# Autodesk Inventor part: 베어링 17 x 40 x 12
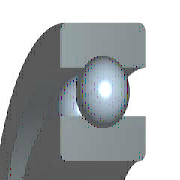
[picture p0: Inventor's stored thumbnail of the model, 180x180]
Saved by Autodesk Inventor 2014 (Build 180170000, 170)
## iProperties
IsCustomPart: 1
Created: 2012-02
Part Number: 베어링 17 x 40 x 12
Material: 강철, 연강
Description: 깊은 그루브 볼 베어링
Document SubType Name: Modeling
Standard: KS B 2023
Designer: mduedu
Standards Organization: KS
Language: ko-KR
Size Designation: 6203 - 17 x 40 x 12
Categories: <MemberInstance><Categories><Category DisplayName="샤프트 부품" InternalName="7f7aeb1f-a693-4053-b835-cee3144e0d98" Mnemonic="SHFT"><Category DisplayName="베어링" Inter
Density: 1 g/cm^3
Appearance: 노란색
Author: mduedu
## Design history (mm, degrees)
sketch "스케치" dims "d0" = 5.98 (= -0.26 x WD + 0.26 x BD)
  geometry: L1 (3.01, 14.25)-(8.99, 14.25); L2 (6, 14.25)-(6, 11.26); L3 (6, 14.25)-(6, 17.24); L4 (3.778, 12.249)-(0, 12.249); L5 (0, 8.5)-(12, 8.5); L6 (3.778, 16.251)-(0, 16.251); L7 (0, 20)-(12, 20); L8 (12, 8.5)-(12, 12.249); L9 (8.222, 12.249)-(12, 12.249); L10 (8.222, 16.251)-(12, 16.251); L11 (12, 20)-(12, 16.251); L12 (-1.4, 0)-(8.4, 0) reference; L13 (0, -0.3)-(0, 5.3) reference
  constraints: 22 end point, 4 point on line, 2 collinear, 2 perpendicular, 2 symmetric about line, 1 midpoint, 1 parallel, 14 other
  dimensions: "d9" = 17 diameter of L5 L12 (= WD); "d11" = 40 diameter of L7 L12 (= BD); "d12" = 12 distance between parallel lines of L8 L13 (= KB); "d13" = 24.498 diameter of L9 L12 (= 0.326 x BD + 0.674 x WD)
revolve "본체" stored, may be unused: angle "d6" = 90 deg
revolve "볼" stored, may be unused: angle "d7" = 90 deg
pattern_circular "IDS_ARRAYBALL[SIMPL:T]" dims angle "d3" = 360 deg
body "Solid1"
fillet "모깎기1" dims "d1" = 0.6 (= KRS)
other parameters: "WD" = 17 [user parameter; used in 5 equation terms], "BD" = 40 [user parameter; used in 5 equation terms], "KB" = 12 [user parameter; used in 1 equation term], "KRS" = 0.6 [user parameter; used in 1 equation term], "d4" = 0, "d5" = 0, "d8" = 0, "d14" = 0, "d15" = 0, "BBA" = 0 [user parameter], "BC0" = 4750000 [user parameter], "BC" = 9560000 [user parameter], "WR" = 8.5 (= 0.5 x WD) [user parameter]
